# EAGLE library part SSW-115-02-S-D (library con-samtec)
THROUGH-HOLE .025" SQ POST SOCKET Source: Samtec SSW.pdf
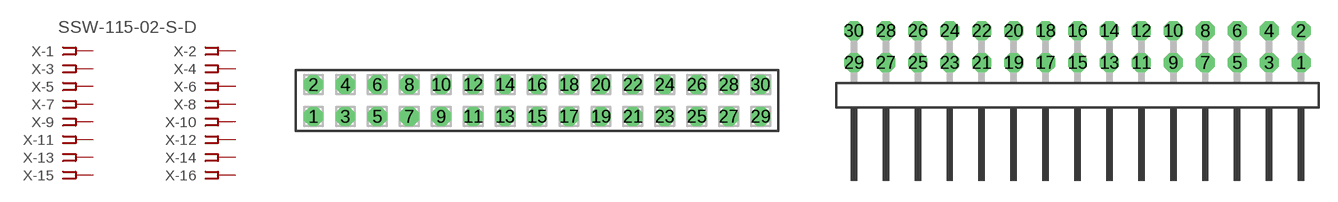
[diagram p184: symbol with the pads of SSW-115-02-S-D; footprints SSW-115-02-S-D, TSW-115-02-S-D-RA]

Designator prefix X; gates -1=FPINV -2=FPIN -3=FPIN -4=FPIN -5=FPIN -6=FPIN -7=FPIN -8=FPIN -9=FPIN -10=FPIN -11=FPIN -12=FPIN -13=FPIN -14=FPIN -15=FPIN -16=FPIN -17=FPIN -18=FPIN -19=FPIN -20=FPIN -21=FPIN -22=FPIN -23=FPIN -24=FPIN -25=FPIN -26=FPIN -27=FPIN -28=FPIN -29=FPIN -30=FPIN

## SSW-115-02-S-D (MPN: SSW-115-02-S-D; OC_FARNELL: unknown; OC_NEWARK: 11P9563)  [SSW-115-02-S-D]
1  -1:1  pas
2  -2:1  pas
3  -3:1  pas
4  -4:1  pas
5  -5:1  pas
6  -6:1  pas
7  -7:1  pas
8  -8:1  pas
9  -9:1  pas
10  -10:1  pas
11  -11:1  pas
12  -12:1  pas
13  -13:1  pas
14  -14:1  pas
15  -15:1  pas
16  -16:1  pas
17  -17:1  pas
18  -18:1  pas
19  -19:1  pas
20  -20:1  pas
21  -21:1  pas
22  -22:1  pas
23  -23:1  pas
24  -24:1  pas
25  -25:1  pas
26  -26:1  pas
27  -27:1  pas
28  -28:1  pas
29  -29:1  pas
30  -30:1  pas

## SSW-115-02-S-D-RA (MPN: SSW-115-02-S-D-RA; OC_FARNELL: unknown; OC_NEWARK: 18M6955)  [TSW-115-02-S-D-RA]
Pads as for SSW-115-02-S-D

## Footprint SSW-115-02-S-D (pad centres in mm)
THROUGH-HOLE .025" SQ POST SOCKET Source: Samtec SSW.pdf
drill 1 pad 1.5 octagon: 1 -17.78,-1.27; 2 -17.78,1.27; 3 -15.24,-1.27; 4 -15.24,1.27; 5 -12.7,-1.27; 6 -12.7,1.27; 7 -10.16,-1.27; 8 -10.16,1.27; 9 -7.62,-1.27; 10 -7.62,1.27; 11 -5.08,-1.27; 12 -5.08,1.27; 13 -2.54,-1.27; 14 -2.54,1.27; 15 0,-1.27; 16 0,1.27; 17 2.54,-1.27; 18 2.54,1.27; 19 5.08,-1.27; 20 5.08,1.27; 21 7.62,-1.27; 22 7.62,1.27; 23 10.16,-1.27; 24 10.16,1.27; 25 12.7,-1.27; 26 12.7,1.27; 27 15.24,-1.27; 28 15.24,1.27; 29 17.78,-1.27; 30 17.78,1.27

## Footprint TSW-115-02-S-D-RA (pad centres in mm)
THROUGH-HOLE .025" SQ POST HEADER Source: Samtec TSW.pdf
drill 1 pad 1.5 octagon: 1 17.78,1.524; 2 17.78,4.064; 3 15.24,1.524; 4 15.24,4.064; 5 12.7,1.524; 6 12.7,4.064; 7 10.16,1.524; 8 10.16,4.064; 9 7.62,1.524; 10 7.62,4.064; 11 5.08,1.524; 12 5.08,4.064; 13 2.54,1.524; 14 2.54,4.064; 15 0,1.524; 16 0,4.064; 17 -2.54,1.524; 18 -2.54,4.064; 19 -5.08,1.524; 20 -5.08,4.064; 21 -7.62,1.524; 22 -7.62,4.064; 23 -10.16,1.524; 24 -10.16,4.064; 25 -12.7,1.524; 26 -12.7,4.064; 27 -15.24,1.524; 28 -15.24,4.064; 29 -17.78,1.524; 30 -17.78,4.064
